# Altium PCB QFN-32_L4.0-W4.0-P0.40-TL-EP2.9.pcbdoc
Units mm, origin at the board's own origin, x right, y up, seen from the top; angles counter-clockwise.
Board outline 17.63 x 17.51 mm, 2 copper layers (Top Layer, Bottom Layer), stack 0 mm thick; 1 components, 0 nets, 33 pads, 0 vias.
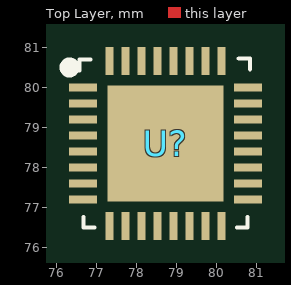
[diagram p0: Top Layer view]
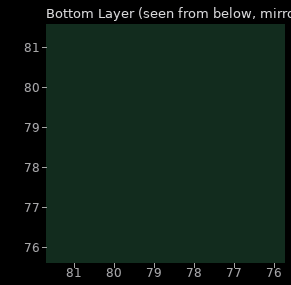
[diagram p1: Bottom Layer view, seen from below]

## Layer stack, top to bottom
Top Layer: signal copper (thickness not stored)
Bottom Layer: signal copper (thickness not stored)

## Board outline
87.482,69.85 69.85,69.85 69.85,87.364 87.482,87.364

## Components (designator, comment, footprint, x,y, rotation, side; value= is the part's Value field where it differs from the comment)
U? "" QFN-32_L4.0-W4.0-P0.40-TL-EP2.9 78.725,78.607 r0 top

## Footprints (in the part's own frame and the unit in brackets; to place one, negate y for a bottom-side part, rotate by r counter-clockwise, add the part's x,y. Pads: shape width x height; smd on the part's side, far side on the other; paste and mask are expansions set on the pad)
QFN-32_L4.0-W4.0-P0.40-TL-EP2.9 [mm]
  rect 0.7x0.2 smd paste-100 mask+0.051: 1(-2.057,1.4) 2(-2.057,1) 3(-2.057,0.6) 4(-2.057,0.2) 5(-2.057,-0.2) 6(-2.057,-0.6) 7(-2.057,-1) 8(-2.057,-1.4) 17(2.057,-1.4) 18(2.057,-1) 19(2.057,-0.6) 20(2.057,-0.2) 21(2.057,0.2) 22(2.057,0.6) 23(2.057,1) 24(2.057,1.4)
  rect 0.2x0.7 smd paste-100 mask+0.051: 9(-1.4,-2.057) 10(-1,-2.057) 11(-0.6,-2.057) 12(-0.2,-2.057) 13(0.2,-2.057) 14(0.6,-2.057) 15(1,-2.057) 16(1.4,-2.057) 25(1.4,2.057) 26(1,2.057) 27(0.6,2.057) 28(0.2,2.057) 29(-0.2,2.057) 30(-0.6,2.057) 31(-1,2.057) 32(-1.4,2.057)
  rect 2.9x2.9 smd paste-100 mask+0.051: 33(0,0)
  silkscreen extent -2.52,-2.1 2.11,2.12

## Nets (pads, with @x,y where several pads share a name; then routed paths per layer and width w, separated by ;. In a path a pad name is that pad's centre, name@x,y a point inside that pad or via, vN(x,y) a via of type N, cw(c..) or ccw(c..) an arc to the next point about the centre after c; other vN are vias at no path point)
pads on no net: U?.1 U?.2 U?.3 U?.4 U?.5 U?.6 U?.7 U?.8 U?.9 U?.10 U?.11 U?.12 U?.13 U?.14 U?.15 U?.16 U?.17 U?.18 U?.19 U?.20 U?.21 U?.22 U?.23 U?.24 U?.25 U?.26 U?.27 U?.28 U?.29 U?.30 U?.31 U?.32 U?.33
